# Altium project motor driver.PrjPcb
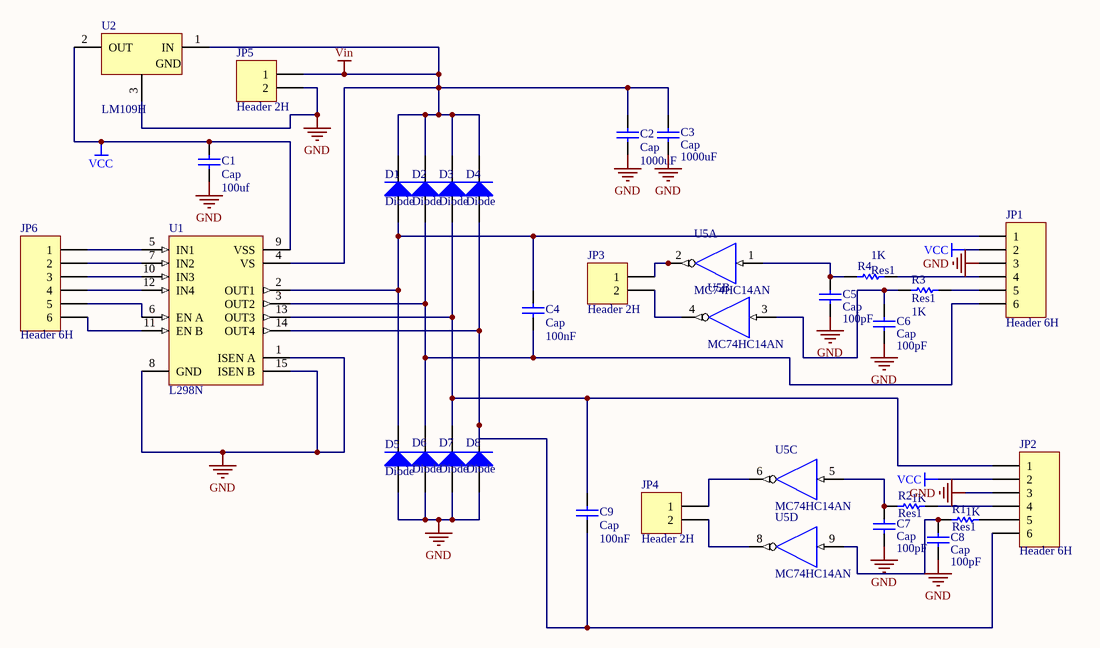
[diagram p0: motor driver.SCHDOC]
1 sheet, 30 parts. Net scope: global (net labels, ports and power ports of the same name join across sheets).
Board file: motor driver_f.PcbDoc

## Sheet motor driver.SCHDOC
size B

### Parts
C1  Cap  value 100uf  [RAD-0.1]
C2  Cap  value 1000uF  [RAD-0.1]
C3  Cap  value 1000uF  [RAD-0.1]
C4  Cap  value 100nF  [RAD-0.1]
C5  Cap  value 100pF  [RAD-0.1]
C6  Cap  value 100pF  [RAD-0.1]
C7  Cap  value 100pF  [RAD-0.1]
C8  Cap  value 100pF  [RAD-0.1]
C9  Cap  value 100nF  [RAD-0.1]
D1  Diode  [AXIAL-0.4]
D2  Diode  [AXIAL-0.4]
D3  Diode  [AXIAL-0.4]
D4  Diode  [AXIAL-0.4]
D5  Diode  [AXIAL-0.4]
D6  Diode  [AXIAL-0.4]
D7  Diode  [AXIAL-0.4]
D8  Diode  [AXIAL-0.4]
JP1  Header 6H  [HDR1X6]
JP2  Header 6H  [HDR1X6]
JP3  Header 2H  [HDR1X2]
JP4  Header 2H  [HDR1X2]
JP5  Header 2H  [HDR1X2]
JP6  Header 6H  [HDR1X6]
R1  Res1  value 1K  [AXIAL-0.3]
R2  Res1  value 1K  [AXIAL-0.3]
R3  Res1  value 1K  [AXIAL-0.3]
R4  Res1  value 1K  [AXIAL-0.3]
U1  L298N  [Multiwatt15V]
U2  LM109H  [HDR1X3]
U5  MC74HC14AN  [646-06]  (parts A,B,C,D of 6)

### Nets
GND: C1.1 C2.1 C3.1 C5.2 C6.2 C7.2 C8.2 D5.1(A) D6.1(A) D7.1(A) D8.1(A) JP1.3 JP2.3 JP5.2 U1.1(ISEN_A) U1.8(GND) U1.15(ISEN_B) U2.3(GND) U5.7(GND)
VCC: C1.2 JP1.2 JP2.2 U1.9(VSS) U2.2(OUT)
VDD: U5.14(VDD)
Vin: C2.2 C3.2 D1.2(K) D2.2(K) D3.2(K) D4.2(K) JP5.1 U1.4(VS) U2.1(IN)
NetC4_1: C4.1 D2.1(A) D6.2(K) JP1.6 U1.3(OUT2)
NetC4_2: C4.2 D1.1(A) D5.2(K) JP1.1 U1.2(OUT1)
NetC5_1: C5.1 R4.1 U5.1(A)
NetC6_1: C6.1 R3.1 U5.3(A)
NetC7_1: C7.1 R2.1 U5.5(A)
NetC8_1: C8.1 R1.1 U5.9(A)
NetC9_1: C9.1 D4.1(A) D8.2(K) JP2.6 U1.14(OUT4)
NetC9_2: C9.2 D3.1(A) D7.2(K) JP2.1 U1.13(OUT3)
NetJP1_4: JP1.4 R4.2
NetJP1_5: JP1.5 R3.2
NetJP2_4: JP2.4 R2.2
NetJP2_5: JP2.5 R1.2
NetJP3_1: JP3.1 U5.2(Y)
NetJP3_2: JP3.2 U5.4(Y)
NetJP4_1: JP4.1 U5.6(Y)
NetJP4_2: JP4.2 U5.8(Y)
NetJP6_1: JP6.1 U1.5(IN1)
NetJP6_2: JP6.2 U1.7(IN2)
NetJP6_3: JP6.3 U1.10(IN3)
NetJP6_4: JP6.4 U1.12(IN4)
NetJP6_5: JP6.5 U1.6(EN_A)
NetJP6_6: JP6.6 U1.11(EN_B)

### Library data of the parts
C1-C9 = Cap: Capacitor; Manufacturer: Generic Components; Class I: Passive
D1-D8 = Diode: Default Diode; Manufacturer: Generic Components; Class I: Discrete; Class II: Diode - Switching
JP1 JP2 JP6 = Header 6H: Header, 6-Pin,  Right Angle; Manufacturer: Generic Components; Class I: Connector
JP3-JP5 = Header 2H: Header, 2-Pin,  Right Angle; Manufacturer: Generic Components; Class I: Connector
R1-R4 = Res1: Resistor; Manufacturer: Generic Components; Class I: Passive
U1 = L298N: Dual Full Bridge Driver
U2 = LM109H: Monolithic Positive Voltage Regulator; pin to pad: 2>3 3>2
U5 = MC74HC14AN: Hex Schmitt Trigger Inverter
